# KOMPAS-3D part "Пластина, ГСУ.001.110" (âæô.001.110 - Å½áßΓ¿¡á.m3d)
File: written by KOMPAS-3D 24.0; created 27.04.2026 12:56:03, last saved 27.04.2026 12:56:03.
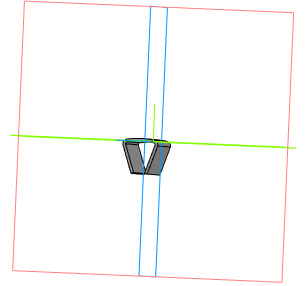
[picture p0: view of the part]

Document properties: Автор: User7; Полное имя файла: C:\Users\User7\Desktop\Двигатель мясорубки\ГСУ.001.110 - Пластина.m3d

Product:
- Part/product: Пластина  | designation ГСУ.001.110
    Масса: 0.002707

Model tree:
1. Эскиз:1
2. Элемент выдавливания:1
     Толщина стенки 1 = 0.5; Расстояние 1 = 38

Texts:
  ГСУ.001.110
